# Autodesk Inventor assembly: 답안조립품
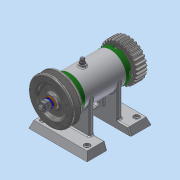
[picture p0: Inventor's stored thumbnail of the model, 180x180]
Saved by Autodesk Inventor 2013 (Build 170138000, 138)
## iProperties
Created: 2016-07
Part Number: 답안조립품
Document SubType Name: Assembly
Designer: dgall
Author: dgall
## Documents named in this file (16)
- C:\Users\dgall\Desktop\460707V1017\답안조립품.iam
- C:\Users\dgall\Desktop\460707V1017\본체.ipt
- C:\Users\dgall\Desktop\460707V1017\축.ipt
- C:\Users\dgall\Desktop\460707V1017\커버.ipt
- C:\Users\dgall\Desktop\460707V1017\베어링 15 x 32 x 9.ipt
- C:\Users\dgall\Desktop\460707V1017\오일 실 15 25 7.ipt
- C:\Users\dgall\Desktop\460707V1017\볼트 M 6 x 8.ipt
- C:\Users\dgall\Desktop\460707V1017\와셔 6x11.5.ipt
- C:\Users\dgall\Desktop\460707V1017\V벨트풀리.ipt
- C:\Users\dgall\Desktop\460707V1017\스퍼기어.ipt
- C:\Users\dgall\Desktop\460707V1017\키 3 x 3 x 12.ipt
- C:\Users\dgall\Desktop\460707V1017\너트 M 8.ipt
- C:\Users\dgall\Desktop\460707V1017\스프링와셔 8.ipt
- C:\Users\dgall\Desktop\460707V1017\와셔 8x17.ipt
- C:\Users\dgall\Desktop\460707V1017\니플 M 6 x 0.75.ipt
- C:\Users\dgall\Desktop\460707V1017\볼트 M4 x 12.ipt
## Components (11 placed, 3 different names)
1. KS B 2023 6002 - 15 x 32 x 9:1
2. KS B 2023 6002 - 15 x 32 x 9:2
3. V벨트풀리:1
4. ISO 4762 M4 x 12:1
5. ISO 4762 M4 x 12:2
6. ISO 4762 M4 x 12:3
7. ISO 4762 M4 x 12:4
8. ISO 4762 M4 x 12:5
9. ISO 4762 M4 x 12:6
10. ISO 4762 M4 x 12:7
11. ISO 4762 M4 x 12:8
